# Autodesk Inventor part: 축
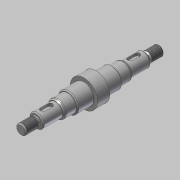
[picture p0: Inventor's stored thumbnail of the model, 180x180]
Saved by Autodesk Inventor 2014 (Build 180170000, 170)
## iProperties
Created: 2019-09
Part Number: 축
Material: 강철, 연강
Document SubType Name: Modeling
Designer: mduedu
Density: 7.86 g/cm^3
Mass: 210.278 g
Surface Area: 69.4769 cm^2
Volume: 26.7529 cm^3
Appearance: Steel
Author: mduedu
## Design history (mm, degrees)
sketch "스케치1"
  geometry: L1 (0, 0)-(15, 0); L2 (15, 0)-(15, 5); L3 (15, 5)-(0, 5); L4 (0, 5)-(0, 0); L5 (15, 0)-(34, 0); L6 (34, 0)-(34, 7); L7 (34, 7)-(15, 7); L8 (15, 7)-(15, 0); L9 (34, 0)-(46, 0); L10 (46, 0)-(46, 8.5); L11 (46, 8.5)-(34, 8.5); L12 (34, 8.5)-(34, 0); L13 (46, 0)-(62, 0); L14 (62, 10)-(46, 10); L15 (46, 10)-(46, 0); L16 (62, 10)-(62, 0); L17 (62, 0)-(68, 0); L18 (68, 0)-(68, 13.5); L19 (68, 13.5)-(62, 13.5); L20 (62, 13.5)-(62, 0)
  constraints: 40 end point, 10 parallel, 5 horizontal, 4 perpendicular, 1 vertical
  dimensions: "d2" = 15 distance of L2.end L3.end; "d3" = 19 distance of L6.end L7.end; "d8" = 16 distance of L14.start L14.end; "d9" = 10 diameter of L3 L1; "d10" = 14 diameter of L7 L5; "d11" = 17 diameter of L11 L9; "d12" = 20 diameter of L14 L13; "d73" = 12 distance of L10.end L11.end (derived); "d74" = 27 diameter of L19 L17; "d75" = 6 distance of L18.end L19.end; "d76" = 68 distance between parallel lines of L4 L18
revolve "회전1" sketch "스케치1" stored, may be unused: angle "d17" = 90 deg
revolve "회전2" stored, may be unused: angle "d22" = 90 deg
fillet "모깎기1" dims "d23" = 0.6
feature "스레드1" dims "d24" = 10, "d25" = 0
chamfer "모따기1" distance "d26" = 1; stored, may be unused: second distance "d27" = 2, angle "d28" = 45 deg
chamfer "모따기2" distance "d29" = 1; stored, may be unused: second distance "d30" = 2, angle "d31" = 45 deg
chamfer "모따기3" distance "d32" = 1.819; stored, may be unused: second distance "d33" = 2, angle "d34" = 30 deg
fillet "모깎기2" dims "d35" = 2
chamfer "모따기4" distance "d36" = 1; stored, may be unused: second distance "d37" = 2, angle "d38" = 30 deg
fillet "모깎기3" dims "d39" = 0.3
node "작업 평면1"
sketch "스케치3" dims "d51" = 12
  geometry: L1 (3, -2.5)-(-4, -2.5); L2 (-4, -2.5)-(-4, 2.5); L3 (-4, 2.5)-(3, 2.5); L4 (3, 2.5)-(3, -2.5); L5 (-9.5, 7.45)-(-9.5, -7.45) reference; 3 further points
  constraints: 8 end point, 2 midpoint, 2 parallel, 2 vertical alignment, 1 horizontal, 1 horizontal alignment, 1 perpendicular, 4 other
  dimensions: "d50" = 3 dimension on L5; "d52" = 5 distance between parallel lines of L3 L1
extrude "돌출1" cut sketch "스케치3" distance "d53" = 3; taper "d54" = 0 deg
node "솔리드1"
mirror "대칭1"
sketch "스케치2"
  geometry: L1 (0, -5)-(0, 5) reference; L2 (0, 5)-(15, 5) reference; L3 (15, 5)-(15, 7) reference; L4 (15, 7)-(34, 7) reference; L5 (34, 7)-(34, 8.5) reference; L6 (34, 8.5)-(46, 8.5) reference; L7 (46, 8.5)-(46, 10) reference; L8 (46, 10)-(62, 10) reference; L9 (62, -10)-(46, -10) reference; L10 (46, -10)-(46, -8.5) reference; L11 (46, -8.5)-(34, -8.5) reference; L12 (34, -8.5)-(34, -7) reference; L13 (34, -7)-(15, -7) reference; L14 (15, -7)-(15, -5) reference; L15 (15, -5)-(0, -5) reference; L16 (0, 0)-(74, 0); L17 (15, 5)-(12.014, 5); L18 (13.4, 4.2)-(15, 4.2); L19 (15, 4.2)-(15, 5); L20 (12.014, 5)-(13.4, 4.2); L21 (62, 10)-(62, 13.5) reference; L22 (62, 13.5)-(68, 13.5) reference; L23 (68, 13.5)-(68, -13.5) reference; L24 (68, -13.5)-(62, -13.5) reference; L25 (62, -13.5)-(62, -10) reference
  constraints: 10 end point, 1 horizontal, 1 parallel, 1 vertical
  dimensions: "d18" = 30 deg angle of L2 L20; "d19" = 8.4 diameter of L18 L16; "d21" = 2.986 distance from line of L17.end L19
node "절단 모서리 투영1"
